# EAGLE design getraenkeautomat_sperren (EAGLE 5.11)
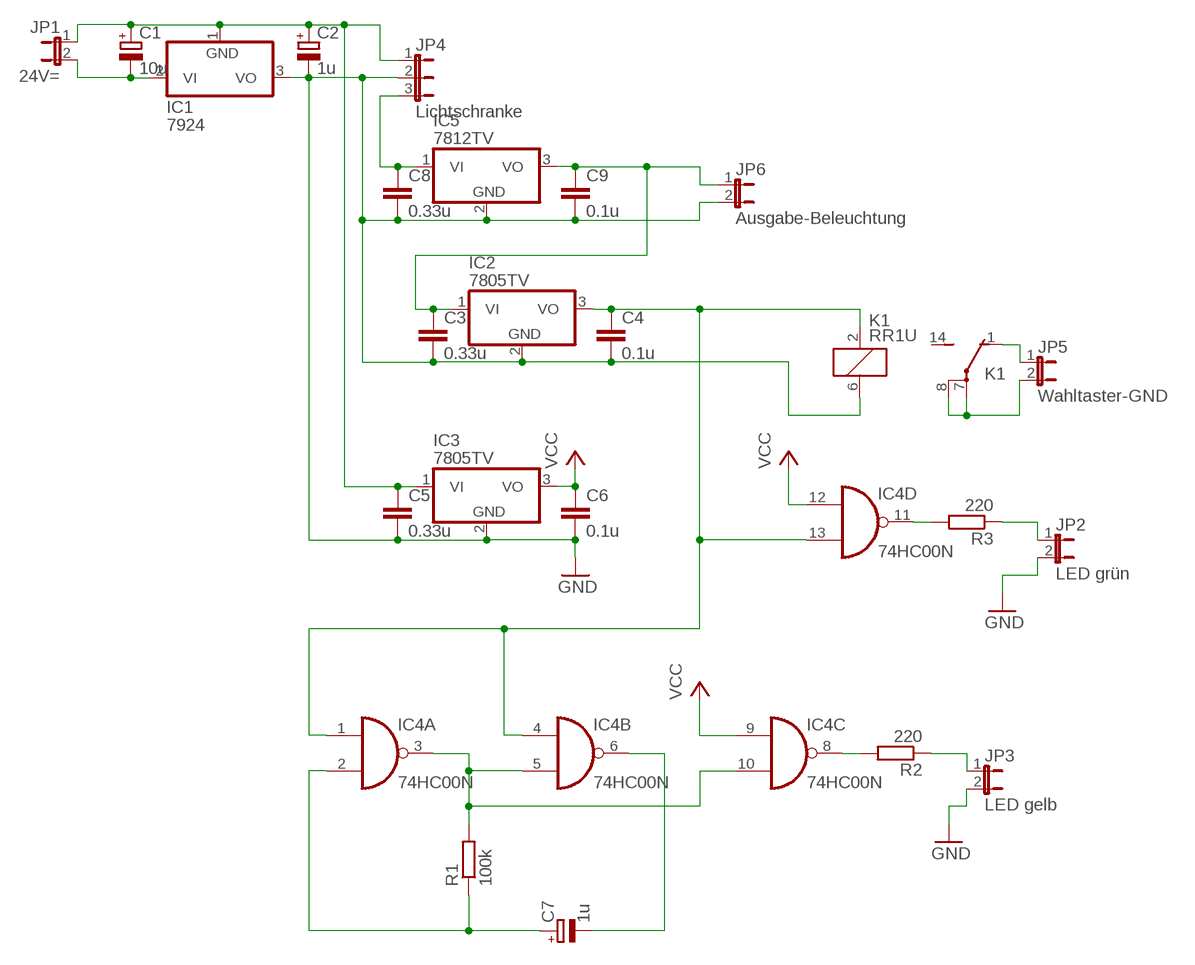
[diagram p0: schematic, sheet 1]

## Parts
C1  10u  CPOL-EUE2,5-6E  [E2,5-6E]
C2  1u  CPOL-EUE2,5-6E  [E2,5-6E]
C3  0.33u  C5/5  [C5B5]
C4  0.1u  C7.5/4  [C7.5B4]
C5  0.33u  C5/5  [C5B5]
C6  0.1u  C7.5/4  [C7.5B4]
C7  1u  CPOL-EUE2,5-6E  [E2,5-6E]
C8  0.33u  C5/5  [C5B5]
C9  0.1u  C7.5/4  [C7.5B4]
IC1  7924  7924T  [TO220H]
IC2  7805TV  [TO220V]
IC3  7805TV  [TO220V]
IC4  74HC00N  [DIL14]
IC5  7812TV  [TO220V]
JP1  24V=  JP1E  [JP1]
JP2  LED grün  JP1E  [JP1]
JP3  LED gelb  JP1E  [JP1]
JP4  Lichtschranke  JP2E  [JP2]
JP5  Wahltaster-GND  JP1E  [JP1]
JP6  Ausgabe-Beleuchtung  JP1E  [JP1]
K1  RR1U  [RR1U]
R1  100k  R-EU_0204/2V  [0204V]
R2  220  R-EU_0204/2V  [0204V]
R3  220  R-EU_0204/2V  [0204V]

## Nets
GND: C2.- C3.2 C4.2 C5.2 C6.2 C8.2 C9.2 IC1.3(VO) IC2.2(GND) IC3.2(GND) IC5.2(GND) JP2.2 JP3.2 JP4.2 JP6.2 K1.6
GND1: JP5.2 K1.7(2:P) K1.8(2:P)
GND2: JP5.1 K1.1(2:O)
N$1: C1.- IC1.2(VI) JP1.2
N$2: IC4.11(D:O) R3.2
N$3: C1.+ C2.+ C5.1 IC1.1(GND) IC3.1(VI) JP1.1 JP4.1
N$4: C3.1 C9.1 IC2.1(VI) IC5.3(VO) JP6.1
N$5: C4.1 IC2.3(VO) IC4.1(A:I0) IC4.4(B:I0) IC4.13(D:I1) K1.2
N$6: IC4.3(A:O) IC4.5(B:I1) IC4.10(C:I1) R1.2
N$7: JP3.1 R2.1
N$8: C7.- IC4.6(B:O)
N$9: C7.+ IC4.2(A:I1) R1.1
N$10: JP2.1 R3.1
N$11: IC4.8(C:O) R2.2
N$12: C8.1 IC5.1(VI) JP4.3
VCC: C6.1 IC3.3(VO) IC4.9(C:I0) IC4.12(D:I0)
Unconnected: K1.14(2:S)

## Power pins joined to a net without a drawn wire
GND: IC4.7(P:GND)
VCC: IC4.14(P:VCC)

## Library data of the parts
C1 C2 C7 = rcl:CPOL-EU: POLARIZED CAPACITOR, European symbol
C3-C6 C8 C9 = capacitor-wima:C: CAPACITOR
IC1 = linear:79*: Negative VOLTAGE REGULATOR
IC2 IC3 IC5 = linear:78*: Positive VOLTAGE REGULATOR Source: http://cache.national.com/ds/LM/LM78L05.pdf http://www.fairchildsemi.com/ds/LM/LM7805.pdf
IC4 = 74xx-eu:74*00: Quad 2-input NAND gate
JP1-JP3 JP5 JP6 = jumper:JP1E: JUMPER
JP4 = jumper:JP2E: JUMPER
K1 = relay:RR1U: RELAY reed, polarity, 1 x switch with shield; OC_FARNELL: unknown; OC_NEWARK: unknown
R1-R3 = rcl:R-EU_: RESISTOR, European symbol

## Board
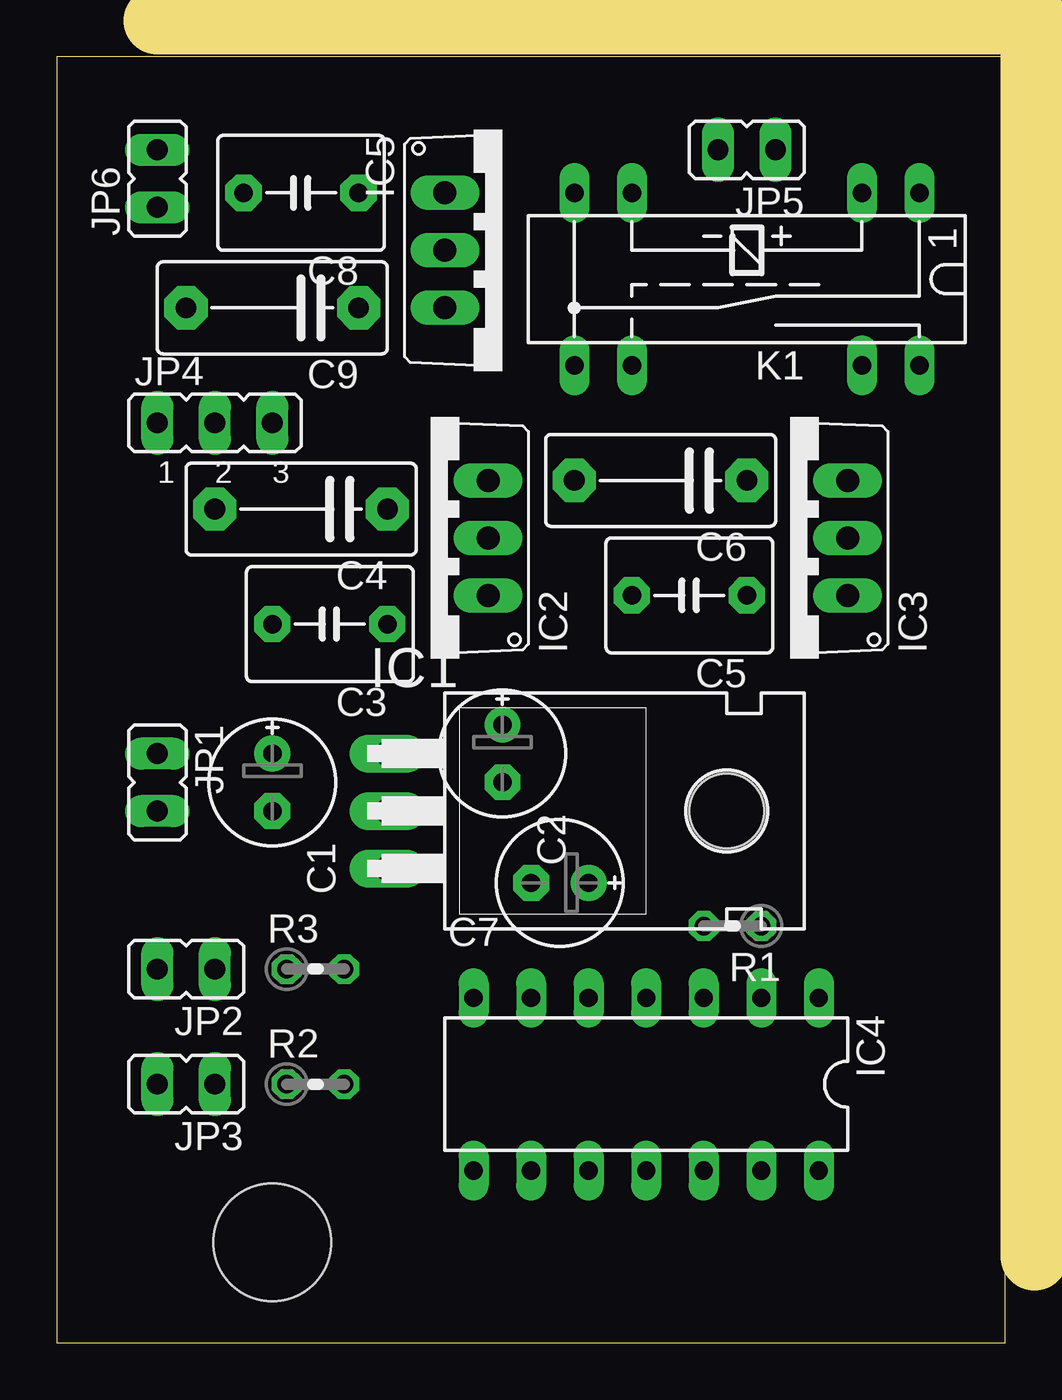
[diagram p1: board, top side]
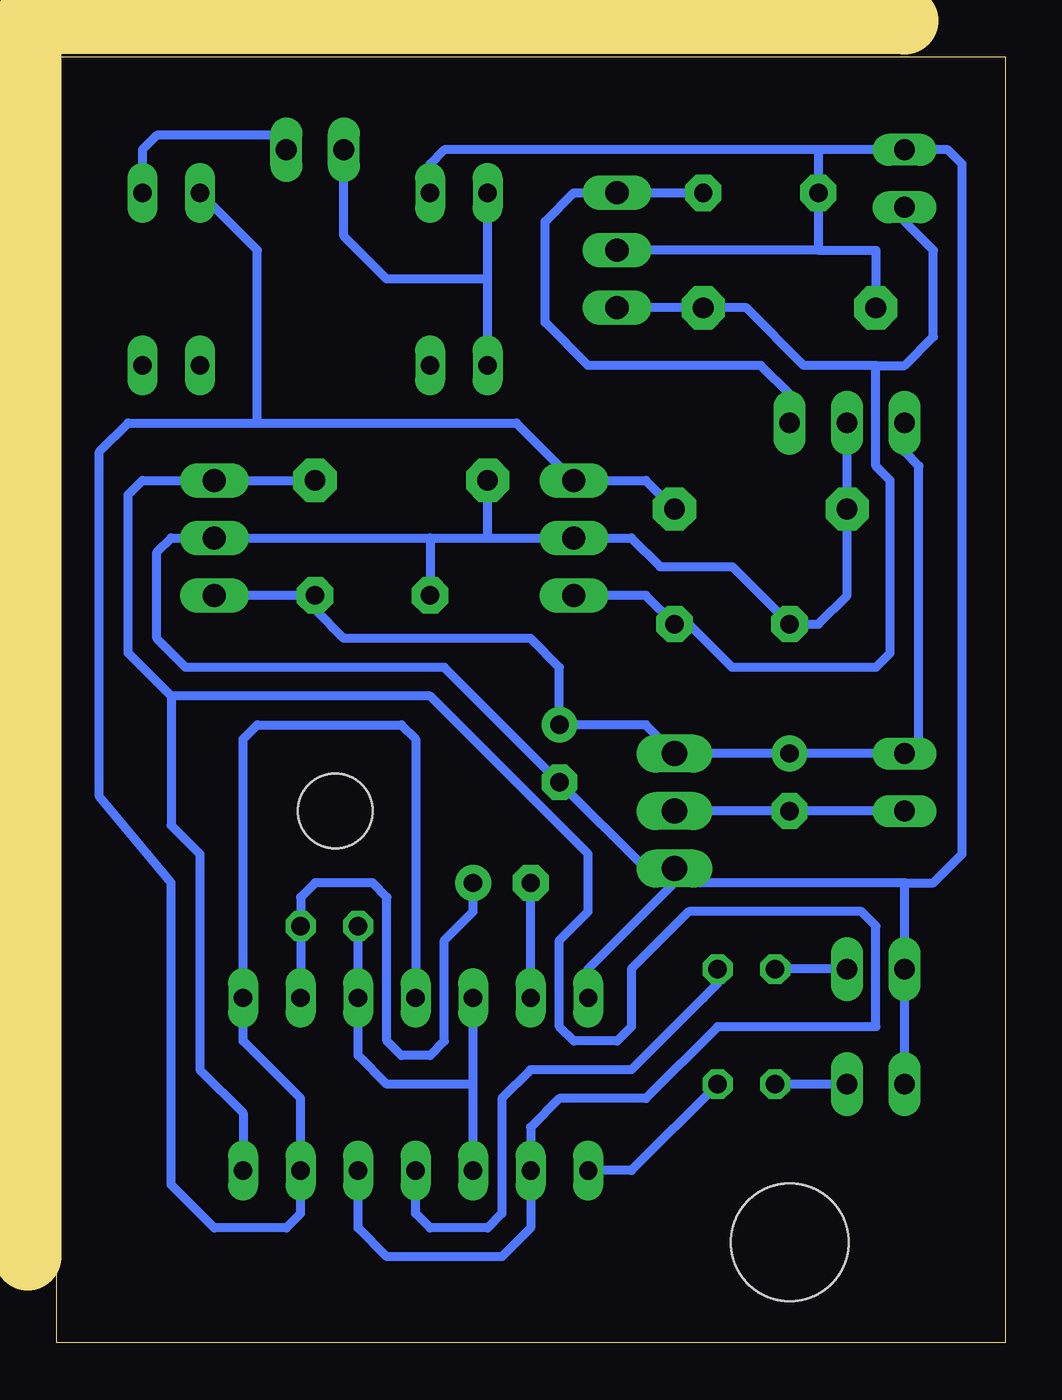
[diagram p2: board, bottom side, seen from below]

Size 41.89 x 56.82 mm. Coordinates in mm from the lower left corner, seen from the top.
Outline: 0,0 41.89,0 41.89,56.82 0,56.82 0,0
Copper layers (1*16): Top 0.035mm / dielectric 1.5mm / Bottom 0.035mm
Design rules "default": minimum track width 10mil, minimum drill 24mil, track to track 8mil, track to pad 8mil, pad to pad 8mil, via to via 8mil, smd to smd 8mil, copper to edge 40mil, drill to drill 8mil, minimum pad ring 10mil, minimum via ring 8mil, stop-mask expansion 4mil, vias tented up to drill 0mil, thermal gap 10mil
Holes 5.2 mm at 9.53,4.45
Milling: 2 lines

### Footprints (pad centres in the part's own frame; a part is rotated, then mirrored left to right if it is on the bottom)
E2,5-6E = drill 0.813 pad 1.575 round: + -1.27,0 | drill 0.813 pad 1.575 octagon: - 1.27,0
C5B5 = drill 0.813 pad 1.6 octagon: 1 -2.54,0; 2 2.54,0
C7.5B4 = drill 0.914 pad 1.905 octagon: 1 -3.81,0; 2 3.81,0
TO220H = drill 1.118 long: 1 -2.54,-10.16; 2 0,-10.16; 3 2.54,-10.16 | hole 3.302: 0,4.826
TO220V = drill 1.016 long: 1 -2.54,-2.54; 2 0,-2.54; 3 2.54,-2.54
DIL14 = drill 0.813 long: 1 -7.62,-3.81; 2 -5.08,-3.81; 3 -2.54,-3.81; 4 0,-3.81; 5 2.54,-3.81; 6 5.08,-3.81; 7 7.62,-3.81; 8 7.62,3.81; 9 5.08,3.81; 10 2.54,3.81; 11 0,3.81; 12 -2.54,3.81; 13 -5.08,3.81; 14 -7.62,3.81
JP1 = drill 0.914 long: 1 0,-1.27; 2 0,1.27
JP2 = drill 0.914 long: 1 -2.54,0; 2 0,0; 3 2.54,0
RR1U = drill 0.813 long: 1 -7.62,-3.81; 2 -5.08,-3.81; 6 5.08,-3.81; 7 7.62,-3.81; 8 7.62,3.81; 9 5.08,3.81; 13 -5.08,3.81; 14 -7.62,3.81
0204V = drill 0.813 octagon: 1 -1.27,0; 2 1.27,0

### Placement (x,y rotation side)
C1  9.53,24.77 270 top
C2  19.68,26.04 270 top
C3  12.06,31.75 180 top
C4  10.79,36.83 180 top
C5  27.94,33.02 180 top
C6  26.67,38.1 180 top
C7  22.23,20.32 180 top
C8  10.79,50.8 180 top
C9  9.53,45.72 180 top
IC1  24.77,23.5 270 top
IC2  16.51,35.56 90 top
IC3  32.38,35.56 90 top
IC4  26.04,11.43 180 top
IC5  19.68,48.26 270 top
JP1  4.45,24.77 180 top
JP2  5.71,16.51 90 top
JP3  5.71,11.43 90 top
JP4  6.99,40.64 0 top
JP5  30.48,52.7 90 top
JP6  4.45,51.44 0 top
K1  30.48,46.99 180 top
R1  29.84,18.41 180 top
R2  11.43,11.43 0 top
R3  11.43,16.51 0 top

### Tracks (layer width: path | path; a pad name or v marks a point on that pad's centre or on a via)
GND
  Bottom 0.406: IC1.3 15.88,20.95 C2.- 24.77,29.84 36.2,29.84 37.47,31.11 37.47,34.92 36.83,35.56 IC3.2 25.4,35.56 | 4.45,20.32 3.17,20.32 1.91,21.59 1.91,52.07 2.54,52.7 JP6.2 8.26,52.7 | 4.45,20.32 13.97,20.32 IC1.3 | JP3.2 JP2.2 4.45,20.32 | IC4.7 18.41,16.51 13.97,20.95 IC1.3 | 25.4,35.56 C5.2 | 22.86,35.56 C6.2 | 25.4,35.56 22.86,35.56 | 8.26,48.26 5.71,48.26 C9.2 | 8.26,48.26 IC5.2 | 8.26,48.26 C8.2 8.26,52.7 | K1.6 25.4,52.07 24.77,52.7 8.26,52.7 | 22.86,35.56 IC2.2 16.51,35.56 15.24,34.29 12.06,34.29 C3.2 8.26,31.75 6.99,33.02 C4.2 JP4.2
GND1
  Bottom 0.406: K1.8 22.86,46.99 | 22.86,46.99 K1.7 | JP5.2 29.21,48.9 27.3,46.99 22.86,46.99
GND2
  Bottom 0.406: K1.1 38.1,52.7 37.47,53.34 32.38,53.34 JP5.1
N$1
  Bottom 0.406: IC1.2 C1.- JP1.2
N$2
  Bottom 0.406: IC4.11 26.04,5.71 25.4,5.08 22.86,5.08 22.23,5.71 22.23,10.79 20.95,12.06 16.51,12.06 13.34,15.24 12.7,15.88 R3.2
N$3
  Bottom 0.406: IC3.1 C5.1 30.48,32.38 29.21,31.11 20.95,31.11 19.68,29.84 C2.+ 15.88,27.3 IC1.1 C1.+ JP1.1 3.81,26.67 3.81,38.73 4.45,39.37 JP4.1
N$4
  Bottom 0.406: IC5.3 C9.1 11.43,45.72 8.89,43.18 5.71,43.18 | 5.71,43.18 4.45,43.18 3.17,44.45 3.17,48.26 4.45,49.53 JP6.1 | IC2.1 15.88,33.02 C3.1 13.97,31.75 12.06,29.84 5.71,29.84 5.08,30.48 5.08,38.1 5.71,38.73 5.71,43.18
N$5
  Bottom 0.406: IC4.4 26.04,26.67 26.67,27.3 33.02,27.3 33.66,26.67 IC4.1 33.66,13.34 31.11,10.79 IC4.13 31.11,5.71 31.75,5.08 34.92,5.08 36.83,6.99 36.83,20.32 40.01,24.13 40.01,39.37 38.73,40.64 33.02,40.64 | 33.02,40.64 21.59,40.64 IC2.3 15.88,38.1 C4.1 | K1.2 33.02,48.26 33.02,40.64
N$6
  Bottom 0.406: 23.5,11.43 IC4.5 | IC4.10 23.5,11.43 | 23.5,11.43 27.3,11.43 28.57,12.7 IC4.3 R1.2
N$7
  Bottom 0.406: JP3.1 R2.1
N$8
  Bottom 0.406: IC4.6 C7.-
N$9
  Bottom 0.406: IC4.2 R1.1 31.11,19.68 30.48,20.32 27.94,20.32 27.3,19.68 27.3,13.34 26.67,12.7 25.4,12.7 24.77,13.34 24.77,17.78 23.5,19.05 C7.+
N$10
  Bottom 0.406: JP2.1 R3.1
N$11
  Bottom 0.406: R2.2 16.51,7.62 IC4.8
N$12
  Bottom 0.406: C8.1 IC5.1 19.05,50.8 20.32,49.53 20.32,45.09 18.41,43.18 10.79,43.18 9.53,41.91 JP4.3
VCC
  Bottom 0.406: IC4.14 33.66,10.16 35.56,12.06 35.56,21.59 36.83,22.86 36.83,28.57 | 36.83,28.57 25.4,28.57 18.41,21.59 18.41,19.05 19.68,17.78 19.68,13.97 19.05,13.34 17.14,13.34 16.51,13.97 16.51,16.51 13.97,19.05 6.35,19.05 5.71,18.41 5.71,13.97 12.7,13.97 15.88,10.79 19.68,10.79 20.95,9.53 IC4.9 20.95,5.08 22.23,3.81 27.3,3.81 28.57,5.08 IC4.12 | C6.1 IC3.3 38.1,38.1 38.73,37.47 38.73,30.48 36.83,28.57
